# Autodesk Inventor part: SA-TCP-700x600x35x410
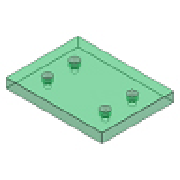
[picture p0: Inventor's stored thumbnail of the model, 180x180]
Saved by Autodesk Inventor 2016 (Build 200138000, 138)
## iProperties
Created: 2015-02
Part Number: SA-TCP-700x600x35x410
Material: S 55 C
Description: Top Clamping Plate
Document SubType Name: Modeling
Designer: Sandeep
Standard Revision: 1
Manufacturer: FUTABA
Language: en-US
Size Designation: 700x600x35x410
Categories: <MemberInstance><Categories><Category DisplayName="Mold" InternalName="349578f2-f4d4-4954-8c09-8e99297a61c0" Mnemonic="MOLD"><Category DisplayName="Mold Plates"
Density: 7.85 g/cm^3
Appearance: Clear - Green 1
IsCustomPart: 1
Author: Sandeep
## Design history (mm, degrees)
sketch "Sketch1"
  geometry: L1 (-300, 350)-(300, 350); L2 (300, 350)-(300, -350); L3 (300, -350)-(-300, -350); L4 (-300, -350)-(-300, 350); 3 further points
  constraints: 8 end point, 2 midpoint, 2 parallel, 1 horizontal, 1 horizontal alignment, 1 perpendicular, 1 vertical alignment
  dimensions: "d72" = 600 distance between parallel lines of L2 L4 (= W_); "d73" = 700 distance between parallel lines of L3 L1 (= L)
extrude "Extrusion1" new body sketch "Sketch1" distance "d20" = 35 (= H_); taper "d30" = 0 deg
feature "Sculpt1"
body "Solid1"
sketch "Sketch2"
  geometry: 2 further points
  dimensions: "d53" = 205 horizontal distance of point (0, 0) point (-205, 243) (= 0.5 x S1_W); "d54" = 243 vertical distance of point (0, 0) point (-205, 243) (= 0.5 x S1_L)
hole "Hole1" sketch "Sketch2" diameter "d55" = 18 (= S1_d1); stored, may be unused: countersink angle "d59" = 90 deg, drill point angle "d61" = 0 deg; dims "d56" = 6, "d57" = 26 (= S1_d2), "d58" = 17.5 (= S1_k), "d60" = 35 (= H_)
pattern_linear "Rectangular Pattern1" dims "d64" = 243 (computed from S1_L, Ns)
chamfer "Chamfer1" distance "d68" = 0.5; stored, may be unused: second distance "d69" = 2, angle "d71" = 45 deg
feature "Surface1"
body "Srf1"
other parameters: "L" = 700 [user parameter; used in 1 equation term], "W_" = 600 [user parameter; used in 1 equation term], "H_" = 35 [user parameter; used in 2 equation terms], "S1_d1" = 18 [user parameter; used in 1 equation term], "S1_d2" = 26 [user parameter; used in 1 equation term], "S1_k" = 17.5 [user parameter; used in 1 equation term], "S1_L" = 486 [user parameter; used in 2 equation terms]
